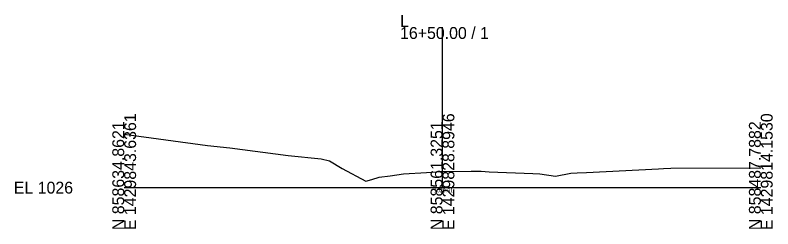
# Model space of a CAD drawing. Extents: x -26 to 153, y -10 to 13058.
# Drawn here: x -25.7 to 152.8, y 9990.3 to 10040.6 of the extents above; entities that cross this region are included whole.
import ezdxf

# ---------------------------------------------------------------- set-up
doc = ezdxf.new("R2010")
doc.units = 0
for name, color, linetype in [('Default', 7, 'Continuous'), ('Exist Cross Section Cell', 7, 'Continuous'), ('Exist XS Center Line Elevation Label', 7, 'Continuous'), ('Exist XS Ground Line', 7, 'Continuous')]:
    doc.layers.add(name, color=color, linetype=linetype)

msp = doc.modelspace()

# ---------------------------------------------------------------- linework, layer by layer
at = {"layer": 'Exist Cross Section Cell'}
for p, q in [((75, 10000), (75, 10037.79)), ((0, 10000), (75, 10000)), ((75, 10000), (150, 10000))]:
    msp.add_line(p, q, dxfattribs=at)
at = {"layer": 'Exist XS Ground Line'}
msp.add_lwpolyline([(0, 10012.6), (19.63, 10009.92), (24.9, 10009.37), (38.63, 10007.6), (46.38, 10006.75), (48.35, 10006.28), (51.34, 10004.54), (56.95, 10001.49), (58.32, 10001.93), (60.04, 10002.43), (62.68, 10002.79), (65.78, 10003.26), (71.22, 10003.6), (74.64, 10003.81), (75, 10003.81), (81.74, 10003.87), (84.13, 10003.9), (85.98, 10003.71), (96.32, 10003.31), (97.95, 10003.24), (101.65, 10002.7), (105.25, 10003.39), (106.76, 10003.45), (108.9, 10003.58), (125.88, 10004.44), (127.07, 10004.5), (128.79, 10004.55), (149.63, 10004.64), (150, 10004.65)], dxfattribs=at)

# ---------------------------------------------------------------- texts
at = {"layer": 'Default'}
msp.add_text('-', height=0.0001, dxfattribs=at).set_placement((0, 10000))
at = {"layer": 'Exist Cross Section Cell'}
for s, p in [('L', (65, 10037.79)), ('16+50.00 / 1', (65, 10034.99)), ('EL 1026', (-26, 9998.6))]:
    msp.add_text(s, height=2.8, dxfattribs=at).set_placement(p)
for s, p in [('E 1429843.6361', (2.8, 9990)), ('E 1429828.8946', (77.8, 9990)), ('E 1429814.1530', (152.8, 9990)), ('N 858634.8621', (0, 9990)), ('N 858561.3251', (75, 9990)), ('N 858487.7882', (150, 9990))]:
    msp.add_text(s, height=2.8, rotation=90, dxfattribs=at).set_placement(p)
at = {"layer": 'Exist XS Center Line Elevation Label'}
msp.add_text('1029.81', height=0.9, dxfattribs=at).set_placement((73, 9998.91))
msp.add_text('1029.81', height=0.9, dxfattribs=at).set_placement((73, 9998.91))
msp.add_text('1029.81', height=0.9, dxfattribs=at).set_placement((73, 9998.91))

doc.saveas('drawing.dxf')
